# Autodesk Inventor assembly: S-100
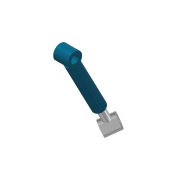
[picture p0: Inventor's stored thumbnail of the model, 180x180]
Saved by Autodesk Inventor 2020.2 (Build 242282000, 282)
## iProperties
Created: 2014-01
Part Number: S-100
Document SubType Name: Assembly
Designer: F.Stasiak
Manager: www.cadconsulting.pl
Company: Fabian Stasiak CAD Consulting
Author: F.Stasiak
Subject: Zbiór ćwiczeń. Autodesk Inventor 2020. Kurs podstawowy
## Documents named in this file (3)
- C:\2020_Kurs_podstawowy\R6 Zespoły\Warsztat\Komponenty\S-100.iam
- C:\2020_Kurs_podstawowy\R6 Zespoły\Warsztat\Komponenty\S-100.ipt
- C:\2020_Kurs_podstawowy\R6 Zespoły\Warsztat\Komponenty\S-101.ipt
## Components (2 placed, 2 different names)
1. S-100:1 — NAPĘD
2. S-101:1 — NAPĘD
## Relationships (1: Mate 1)
- NAPĘD [Mate]: S-100:1 ↔ S-101:1
